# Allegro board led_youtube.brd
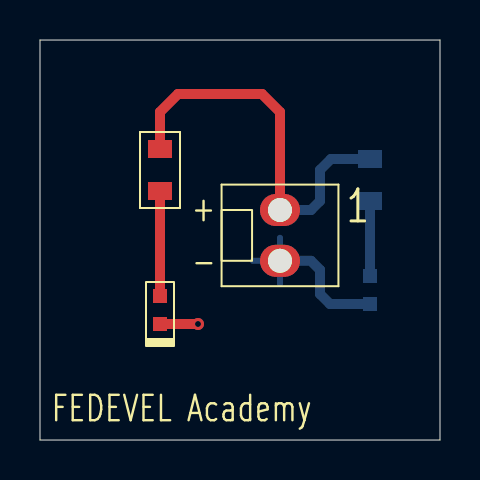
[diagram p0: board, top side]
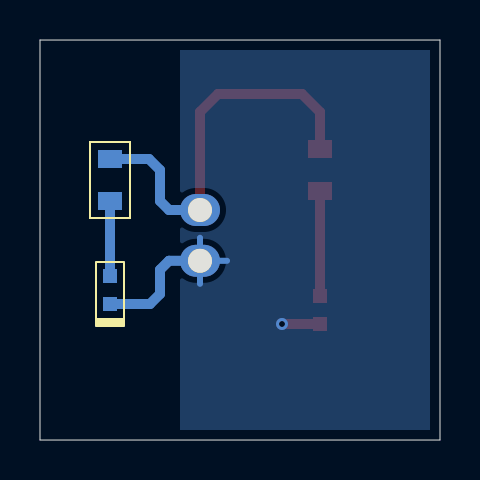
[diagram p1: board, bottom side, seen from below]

Outline 20 x 20 mm; copper layers: TOP, BOTTOM. Coordinates in mm from the lower left corner of the outline.
Outline path: 0,20 20,20 20,0 0,0 0,20

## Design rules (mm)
constraint set DEFAULT: min track width 0.3

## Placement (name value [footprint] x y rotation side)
D1  Green  [LED0603G]  6 6.5 90 top
D2  Green  [LED0603G]  16.5 7.5 90 bottom
J1  1x2 Header  [HDR1X2]  12 11.5 0 top
R1  360R 1%  [R0805]  6 13.5 270 top
R2  360R 1%  [R0805]  16.5 13 270 bottom

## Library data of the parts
D1 D2 = LED SM 0603 3V GREEN
J1 = CONN HEADER VERT 2POS 2.54MM
R1 R2 = RES SMD 360 OHM 1% 1/8W 0805

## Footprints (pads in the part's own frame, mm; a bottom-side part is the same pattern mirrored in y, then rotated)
HDR1X2
  oval 2x1.6 hole 1.2: 1(0,0) 2(0,-2.54)
LED0603G
  rect 0.7x0.7 smd: 1(-0.7,0) 2(0.7,0)
R0805
  rect 0.9x1.2 smd: 1(-1.05,0) 2(1.05,0)

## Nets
+3V3: J1.1 R1.1 R2.1
GND: D1.1(C) D2.1(C) J1.2(-)
DIODE1: D1.2 R1.2
DIODE2: D2.2 R2.2

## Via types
v1: diameter 0.6, hole 0.3, TOP to BOTTOM, 1 via

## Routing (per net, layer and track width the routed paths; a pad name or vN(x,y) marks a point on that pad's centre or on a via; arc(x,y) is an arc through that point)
+3V3: length 20
  TOP w0.5: R1.1 6,16.4 6.9,17.3 11.1,17.3 12,16.4 J1.1
  BOTTOM w0.5: J1.1 13.55,11.5 14,11.95 14,13.5 14.55,14.05 R2.1
GND: length 11.7
  TOP w0.5: D1.1 v1(7.9,5.8)
  BOTTOM w0.3: 12,7.81 J1.2 ; J1.2 12,10.11 ; J1.2 10.65,8.96
  BOTTOM w0.5: J1.2 13.55,8.96 14,8.51 14,7.3 14.5,6.8 D2.1
DIODE1: length 5.2
  TOP w0.5: R1.2 D1.2
DIODE2: length 3.8
  BOTTOM w0.5: R2.2 D2.2

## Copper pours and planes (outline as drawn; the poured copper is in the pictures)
GND on BOTTOM: 0.5,0.5 0.5,19.5 13,19.5 13,0.5

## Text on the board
Ref Des/Silkscreen Top: FEDEVEL Academy | + | -
